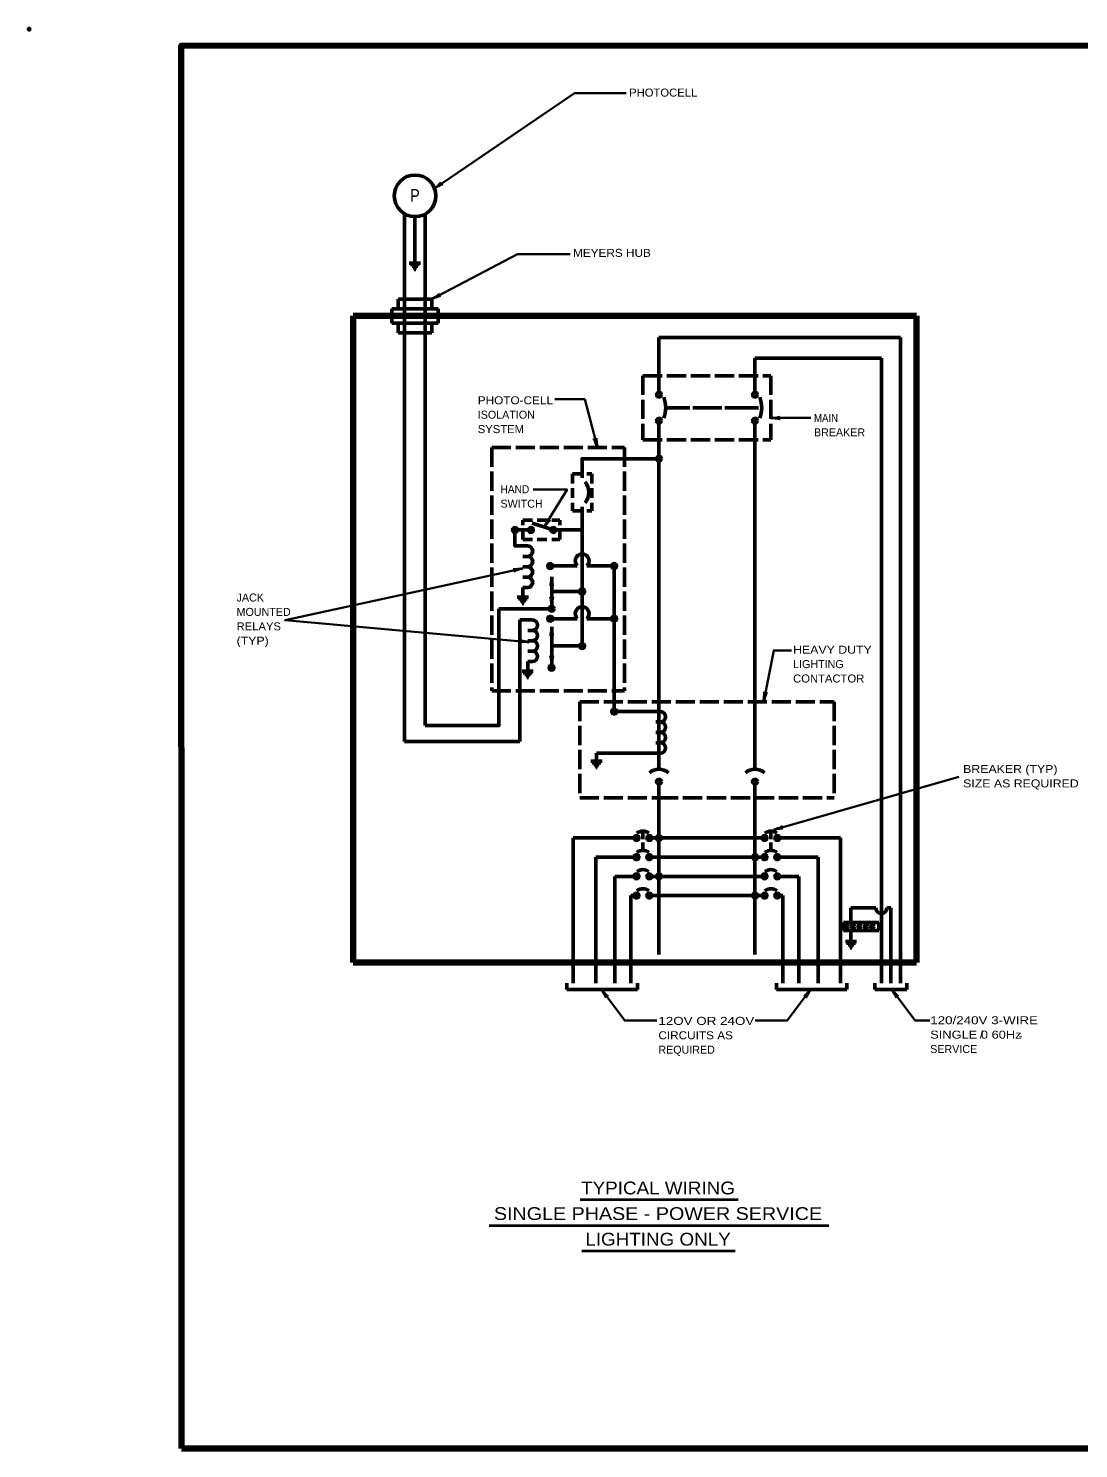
# Model space of a CAD drawing. Extents: x -35 to 821, y -18 to 526.
# Drawn here: x -35 to 359, y -7 to 526 of the extents above; entities that cross this region are included whole.
import ezdxf
from ezdxf.enums import TextEntityAlignment as Align

# ---------------------------------------------------------------- set-up
doc = ezdxf.new("R2010")
doc.units = 0
doc.header["$LTSCALE"] = 1.2
doc.header["$PDMODE"] = 32
doc.header["$PDSIZE"] = 0.6
doc.linetypes.add('LONG_DASHED', pattern=[7.5, 6, -1.5])
doc.linetypes.add('MEDIUM_DASHED', pattern=[4.5, 3, -1.5])
doc.layers.add('1', color=7, linetype='Continuous', lineweight=53)

msp = doc.modelspace()

# ---------------------------------------------------------------- hatches: boundary and pattern name
at = {"layer": '1'}
for points in [[(202.751, 364.268, 1), (200.951, 364.268, 1)], [(148.751, 337.568, 1), (146.951, 337.568, 1)], [(154.751, 337.568, 1), (152.951, 337.568, 1)], [(163.151, 337.568, 1), (161.351, 337.568, 1)], [(161.951, 324.068, 1), (160.151, 324.068, 1)], [(185.951, 324.068, 1), (184.151, 324.068, 1)], [(173.951, 314.468, 1), (172.151, 314.468, 1)], [(162.551, 308.018, 1), (160.751, 308.018, 1)], [(161.951, 304.268, 1), (160.151, 304.268, 1)], [(185.951, 304.268, 1), (184.151, 304.268, 1)], [(173.951, 294.068, 1), (172.151, 294.068, 1)], [(162.468, 285.943, 1), (160.668, 285.943, 1)], [(185.951, 269.468, 1), (184.151, 269.468, 1)], [(194.351, 222.068, 1), (192.551, 222.068, 1)], [(199.151, 222.068, 1), (197.351, 222.068, 1)], [(202.751, 222.068, 1), (200.951, 222.068, 1)], [(242.351, 222.068, 1), (240.551, 222.068, 1)], [(247.151, 222.068, 1), (245.351, 222.068, 1)], [(194.351, 214.868, 1), (192.551, 214.868, 1)], [(199.151, 214.868, 1), (197.351, 214.868, 1)], [(238.751, 214.868, 1), (236.951, 214.868, 1)], [(242.351, 214.868, 1), (240.551, 214.868, 1)], [(247.151, 214.868, 1), (245.351, 214.868, 1)], [(194.351, 207.668, 1), (192.551, 207.668, 1)], [(199.151, 207.668, 1), (197.351, 207.668, 1)], [(202.751, 207.668, 1), (200.951, 207.668, 1)], [(242.351, 207.668, 1), (240.551, 207.668, 1)], [(247.151, 207.668, 1), (245.351, 207.668, 1)], [(194.351, 200.468, 1), (192.551, 200.468, 1)], [(199.151, 200.468, 1), (197.351, 200.468, 1)], [(238.751, 200.468, 1), (236.951, 200.468, 1)], [(242.351, 200.468, 1), (240.551, 200.468, 1)], [(247.151, 200.468, 1), (245.351, 200.468, 1)], [(272.843, 188.918, 1), (271.642, 188.918, 1)], [(275.243, 188.918, 1), (274.043, 188.918, 1)], [(277.643, 188.918, 1), (276.442, 188.918, 1)], [(280.043, 188.918, 1), (278.842, 188.918, 1)], [(282.443, 188.918, 1), (281.243, 188.918, 1)]]:
    msp.add_hatch(color=256, dxfattribs=at).paths.add_polyline_path(points)

# ---------------------------------------------------------------- linework, layer by layer
for p, q in [((106.451, 456.122), (106.451, 258.218)), ((110.351, 437.638), (110.351, 455.038)), ((114.251, 456.044), (114.251, 264.218)), ((108.251, 437.638), (112.451, 437.638)), ((108.701, 437.038), (112.001, 437.038)), ((109.301, 436.438), (111.401, 436.438)), ((109.751, 435.838), (110.951, 435.838)), ((110.051, 435.238), (110.651, 435.238)), ((104.051, 424.118), (116.651, 424.118)), ((104.051, 424.118), (104.051, 420.518)), ((116.651, 424.118), (116.651, 420.518)), ((101.651, 420.518), (119.051, 420.518)), ((101.651, 420.518), (101.651, 415.118)), ((119.051, 420.518), (119.051, 415.118)), ((101.651, 415.118), (119.051, 415.118)), ((104.051, 411.518), (104.051, 415.118)), ((104.051, 411.518), (116.651, 411.518)), ((116.651, 411.518), (116.651, 415.118)), ((201.851, 409.718), (292.451, 409.718)), ((292.451, 409.718), (292.451, 167.618)), ((237.851, 401.918), (285.251, 401.918)), ((237.851, 389.168), (237.851, 401.918)), ((285.251, 401.918), (285.251, 167.618)), ((204.397, 383.393), (213.397, 383.393)), ((214.597, 383.393), (225.397, 383.393)), ((226.597, 383.393), (239.197, 383.393)), ((201.851, 377.618), (201.851, 247.868)), ((237.851, 377.618), (237.851, 247.868)), ((173.051, 314.468), (173.051, 346.268)), ((153.851, 337.568), (147.851, 337.568)), ((162.251, 337.568), (154.262, 340.164)), ((173.051, 337.568), (162.251, 337.568)), ((150.851, 327.668), (152.651, 327.668)), ((150.851, 323.768), (152.651, 323.768)), ((150.851, 319.868), (152.651, 319.868)), ((171.251, 324.068), (161.051, 324.068)), ((161.651, 308.918), (161.651, 320.018)), ((150.851, 315.968), (152.651, 315.968)), ((150.851, 315.968), (150.851, 312.368)), ((173.051, 314.468), (161.651, 314.468)), ((148.751, 312.368), (152.951, 312.368)), ((149.201, 311.768), (152.501, 311.768)), ((149.801, 311.168), (151.901, 311.168)), ((150.251, 310.568), (151.451, 310.568)), ((150.551, 309.968), (151.151, 309.968)), ((141.851, 308.018), (161.651, 308.018)), ((149.651, 258.218), (149.651, 303.818)), ((149.651, 303.818), (154.451, 303.818)), ((171.251, 304.268), (161.051, 304.268)), ((185.051, 304.268), (174.851, 304.268)), ((152.651, 299.918), (154.451, 299.918)), ((161.651, 286.868), (161.651, 301.268)), ((152.651, 296.018), (154.451, 296.018)), ((152.651, 292.118), (154.451, 292.118)), ((152.651, 288.218), (154.451, 288.218)), ((152.651, 288.218), (152.651, 284.618)), ((150.551, 284.618), (154.751, 284.618)), ((151.001, 284.018), (154.301, 284.018)), ((151.601, 283.418), (153.701, 283.418)), ((152.051, 282.818), (153.251, 282.818)), ((152.351, 282.218), (152.951, 282.218)), ((201.851, 269.468), (202.451, 269.468)), ((200.651, 265.568), (202.451, 265.568)), ((200.651, 261.668), (202.451, 261.668)), ((106.451, 258.218), (149.651, 258.218)), ((200.651, 257.768), (202.451, 257.768)), ((176.351, 250.868), (180.551, 250.868)), ((178.451, 253.868), (202.451, 253.868)), ((178.451, 253.868), (178.451, 250.868)), ((176.801, 250.268), (180.101, 250.268)), ((177.401, 249.668), (179.501, 249.668)), ((177.851, 249.068), (179.051, 249.068)), ((178.151, 248.468), (178.751, 248.468)), ((201.851, 242.318), (201.851, 178.418)), ((237.851, 242.318), (237.851, 178.418)), ((195.851, 224.012), (195.851, 221.612)), ((243.851, 224.012), (243.851, 221.612)), ((169.751, 222.068), (169.751, 167.618)), ((169.751, 222.068), (193.451, 222.068)), ((195.851, 220.412), (195.851, 218.012)), ((198.251, 222.068), (241.451, 222.068)), ((243.851, 220.412), (243.851, 218.012)), ((246.251, 222.068), (269.951, 222.068)), ((269.951, 222.068), (269.951, 167.618)), ((178.151, 214.868), (193.451, 214.868)), ((178.151, 214.868), (178.151, 167.618)), ((198.251, 214.868), (241.451, 214.868)), ((246.251, 214.868), (261.551, 214.868)), ((261.551, 214.868), (261.551, 167.618)), ((185.351, 207.668), (193.451, 207.668)), ((185.351, 207.668), (185.351, 167.618)), ((198.251, 207.668), (241.451, 207.668)), ((246.251, 207.668), (254.351, 207.668)), ((254.351, 207.668), (254.351, 167.618)), ((191.351, 200.468), (193.451, 200.468)), ((191.351, 200.468), (191.351, 167.618)), ((198.251, 200.468), (241.451, 200.468)), ((246.251, 200.468), (248.351, 200.468)), ((248.351, 200.468), (248.351, 167.618)), ((273.851, 195.818), (283.151, 195.818)), ((273.851, 195.818), (273.851, 190.418)), ((288.851, 195.818), (287.351, 195.818)), ((288.851, 195.818), (288.851, 167.618)), ((271.043, 190.418), (284.243, 190.418)), ((271.043, 190.418), (271.043, 187.418)), ((271.043, 187.418), (284.243, 187.418)), ((273.851, 187.418), (273.851, 183.218)), ((284.243, 190.418), (284.243, 187.418)), ((271.751, 183.218), (275.951, 183.218)), ((272.201, 182.618), (275.501, 182.618)), ((272.801, 182.018), (274.901, 182.018)), ((273.251, 181.418), (274.451, 181.418)), ((273.551, 180.818), (274.151, 180.818)), ((167.351, 165.218), (167.351, 167.618)), ((167.351, 165.218), (193.751, 165.218)), ((193.751, 165.218), (193.751, 167.618)), ((245.951, 165.218), (245.951, 167.618)), ((245.951, 165.218), (272.351, 165.218)), ((272.351, 165.218), (272.351, 167.618)), ((282.851, 165.218), (282.851, 167.618)), ((282.851, 165.218), (294.851, 165.218)), ((294.851, 165.218), (294.851, 167.618))]:
    msp.add_line(p, q, dxfattribs=at)
at = {"layer": '1', "lineweight": 140}
for p, q in [((87.251, 417.818), (87.251, 175.418)), ((87.251, 417.818), (298.451, 417.818)), ((298.451, 417.818), (298.451, 175.418)), ((87.251, 175.418), (298.451, 175.418))]:
    msp.add_line(p, q, dxfattribs=at)
at = {"layer": '1', "linetype": 'LONG_DASHED'}
for p, q in [((195.851, 395.393), (243.851, 395.393)), ((195.851, 395.393), (195.851, 371.393)), ((243.851, 395.393), (243.851, 371.393)), ((139.151, 368.468), (188.951, 368.468)), ((139.151, 368.468), (139.151, 277.268)), ((188.951, 368.468), (188.951, 277.268)), ((195.851, 371.393), (243.851, 371.393)), ((139.151, 277.268), (188.951, 277.268)), ((172.151, 273.068), (267.551, 273.068)), ((172.151, 273.068), (172.151, 237.068)), ((267.551, 273.068), (267.551, 237.068))]:
    msp.add_line(p, q, dxfattribs=at)
at = {"layer": '1', "lineweight": 35}
for p, q in [((243.851, 379.548), (258.801, 379.548)), ((244.885, 225.129), (314.285, 244.932))]:
    msp.add_line(p, q, dxfattribs=at)
at = {"layer": '1', "linetype": 'MEDIUM_DASHED'}
for p, q in [((169.451, 358.568), (176.651, 358.568)), ((169.451, 358.568), (169.451, 344.768)), ((176.651, 358.568), (176.651, 344.768)), ((150.851, 333.968), (150.851, 341.168)), ((150.851, 341.168), (164.651, 341.168)), ((164.651, 333.968), (164.651, 341.168)), ((169.451, 344.768), (176.651, 344.768)), ((150.851, 333.968), (164.651, 333.968))]:
    msp.add_line(p, q, dxfattribs=at)
at = {"layer": '1', "lineweight": 40}
for p, q in [((172.267, 86.576), (231.603, 86.576)), ((138.189, 76.743), (265.56, 76.743)), ((172.922, 67.237), (230.423, 67.237))]:
    msp.add_line(p, q, dxfattribs=at)
at = {"layer": '1', "lineweight": 158}
msp.add_line((814.433, -6.884), (22.833, -6.884), dxfattribs=at)
msp.add_lwpolyline([(814.433, 519.216), (22.733, 519.116), (22.833, -6.884)], dxfattribs=at)
at = {"layer": '1', "lineweight": 35}
for points in [[(117.696, 465.646), (170.154, 501.283), (189.594, 501.283)], [(116.651, 424.118), (148.77, 440.999), (168.599, 440.999)], [(178.757, 368.468), (174.042, 386.549), (162.767, 386.549)], [(158.855, 338.672), (167.433, 352.712), (154.739, 352.712)], [(150.714, 323.153), (61.678, 303.707), (153.047, 295.539)], [(241.121, 273.414), (244.913, 292.385), (251.523, 292.385)], [(180.361, 165.22), (189.063, 153.575), (201.058, 153.575)], [(258.679, 165.22), (249.977, 153.575), (237.982, 153.575)], [(289.2, 165.22), (297.902, 153.575), (303.472, 153.575)]]:
    msp.add_lwpolyline(points, dxfattribs=at)
at = {"layer": '1'}
for points in [[(201.851, 389.168), (201.851, 401.918), (201.851, 409.718)], [(173.051, 357.068), (173.051, 364.268), (201.851, 364.268)], [(147.851, 337.568), (147.851, 331.568), (152.651, 331.568)], [(185.051, 304.268), (185.051, 324.068), (174.851, 324.068)], [(173.051, 314.468), (173.051, 294.068), (161.651, 294.068)], [(114.251, 264.218), (141.851, 264.218), (141.851, 308.018)], [(185.051, 304.268), (185.051, 269.468), (201.851, 269.468)]]:
    msp.add_lwpolyline(points, dxfattribs=at)
at = {"layer": '1', "linetype": 'LONG_DASHED'}
msp.add_lwpolyline([(172.151, 237.068), (201.851, 237.068), (237.851, 237.068), (267.551, 237.068)], dxfattribs=at)
at = {"layer": '1'}
for centre, radius in [((110.419, 462.838), 7.8), ((201.851, 388.268), 0.9), ((237.851, 388.268), 0.9), ((201.851, 378.518), 0.9), ((237.851, 378.518), 0.9), ((201.851, 364.268), 0.9), ((147.851, 337.568), 0.9), ((153.851, 337.568), 0.9), ((162.251, 337.568), 0.9), ((161.051, 324.068), 0.9), ((185.051, 324.068), 0.9), ((173.051, 314.468), 0.9), ((161.651, 308.018), 0.9), ((161.051, 304.268), 0.9), ((185.051, 304.268), 0.9), ((173.051, 294.068), 0.9), ((161.568, 285.943), 0.9), ((185.051, 269.468), 0.9), ((201.851, 243.218), 0.9), ((237.851, 243.218), 0.9), ((193.451, 222.068), 0.9), ((198.251, 222.068), 0.9), ((201.851, 222.068), 0.9), ((241.451, 222.068), 0.9), ((246.251, 222.068), 0.9), ((193.451, 214.868), 0.9), ((198.251, 214.868), 0.9), ((237.851, 214.868), 0.9), ((241.451, 214.868), 0.9), ((246.251, 214.868), 0.9), ((193.451, 207.668), 0.9), ((198.251, 207.668), 0.9), ((201.851, 207.668), 0.9), ((241.451, 207.668), 0.9), ((246.251, 207.668), 0.9), ((193.451, 200.468), 0.9), ((198.251, 200.468), 0.9), ((237.851, 200.468), 0.9), ((241.451, 200.468), 0.9), ((246.251, 200.468), 0.9), ((272.243, 188.918), 0.6), ((274.643, 188.918), 0.6), ((277.043, 188.918), 0.6), ((279.442, 188.918), 0.6), ((281.843, 188.918), 0.6)]:
    msp.add_circle(centre, radius, dxfattribs=at)
for centre, radius, start, end in [((193.433, 383.393), 10.964, 338.74274, 21.25726), ((229.433, 383.393), 10.964, 338.74274, 21.25726), ((169.048, 351.668), 6.503, 323.14889, 36.85111), ((152.568, 329.618), 1.952, 272.45324, 87.54675), ((152.568, 325.718), 1.952, 272.45324, 87.54675), ((173.051, 325.951), 2.604, 313.71808, 226.28192), ((152.568, 321.818), 1.952, 272.45324, 87.54675), ((152.568, 317.918), 1.952, 272.45324, 87.54675), ((154.368, 301.868), 1.952, 272.45324, 87.54675), ((173.051, 306.151), 2.604, 313.71808, 226.28192), ((154.368, 297.968), 1.952, 272.45324, 87.54675), ((154.368, 294.068), 1.952, 272.45324, 87.54675), ((154.368, 290.168), 1.952, 272.45324, 87.54675), ((202.368, 267.518), 1.952, 272.45324, 87.54675), ((202.368, 263.618), 1.952, 272.45324, 87.54675), ((202.368, 259.718), 1.952, 272.45324, 87.54675), ((202.368, 255.818), 1.952, 272.45324, 87.54675), ((201.851, 242.393), 5.475, 48.88791, 131.11209), ((237.851, 242.393), 5.475, 48.88791, 131.11209), ((195.851, 220.837), 3.775, 53.41416, 126.58584), ((243.851, 220.837), 3.775, 53.41416, 126.58584), ((195.851, 213.637), 3.775, 53.41416, 126.58584), ((243.851, 213.637), 3.775, 53.41416, 126.58584), ((195.851, 206.437), 3.775, 53.41416, 126.58584), ((243.851, 206.437), 3.775, 53.41416, 126.58584), ((195.851, 199.237), 3.775, 53.41416, 126.58584), ((243.851, 199.237), 3.775, 53.41416, 126.58584), ((285.251, 195.841), 2.1, 180.62582, 359.37418)]:
    msp.add_arc(centre, radius, start, end, dxfattribs=at)
at = {"layer": '1', "lineweight": 40}
for centre, major_axis, ratio, start_param, end_param in [((118.593, 466.656), (-1.667, -1.359), 0.122415, 0.8963533, 3.1415927), ((118.951, 466.192), (1.862, 1.01), 0.07063, 6.2823074, 8.5597026), ((117.656, 425.021), (-1.81, -1.163), 0.122415, 0.8963533, 3.1415927), ((117.656, 425.021), (-1.81, -1.163), 0.122415, 0.8963533, 3.1415927), ((117.96, 424.519), (-1.964, -0.794), 0.07063, 3.1407148, 5.41811), ((117.96, 424.519), (-1.964, -0.794), 0.07063, 3.1407148, 5.41811), ((245.196, 379.294), (-2.108, 0.211), 0.07063, 3.1407148, 5.41811), ((245.196, 379.294), (-2.108, 0.211), 0.07063, 3.1407148, 5.41811), ((245.161, 379.879), (-2.143, -0.187), 0.122415, 0.8963533, 3.1415927), ((245.161, 379.879), (-2.143, -0.187), 0.122415, 0.8963533, 3.1415927), ((178.106, 369.652), (0.722, -2.026), 0.122415, 0.8963533, 3.1415927), ((178.106, 369.652), (0.722, -2.026), 0.122415, 0.8963533, 3.1415927), ((178.664, 369.834), (0.328, -2.093), 0.07063, 3.1407148, 5.41811), ((178.664, 369.834), (0.328, -2.093), 0.07063, 3.1407148, 5.41811), ((159.255, 339.962), (-0.957, -1.926), 0.122415, 0.8963533, 3.1415927), ((159.255, 339.962), (-0.957, -1.926), 0.122415, 0.8963533, 3.1415927), ((159.773, 339.687), (1.279, 1.689), 0.07063, 6.2823074, 8.5597026), ((159.773, 339.687), (1.279, 1.689), 0.07063, 6.2823074, 8.5597026), ((149.346, 323.114), (-2.104, -0.244), 0.07063, 6.2823074, 8.5597026), ((149.346, 323.114), (-2.104, -0.244), 0.07063, 6.2823074, 8.5597026), ((149.505, 322.55), (2.054, 0.64), 0.122415, 0.8963533, 3.1415927), ((149.505, 322.55), (2.054, 0.64), 0.122415, 0.8963533, 3.1415927), ((161.397, 318.674), (0.211, 2.108), 0.07063, 3.1407148, 5.41811), ((161.983, 318.709), (-0.187, 2.143), 0.122415, 0.8963533, 3.1415927), ((161.32, 310.228), (0.187, -2.143), 0.122415, 0.8963533, 3.1415927), ((161.905, 310.263), (-0.211, -2.108), 0.07063, 3.1407148, 5.41811), ((161.397, 299.924), (0.211, 2.108), 0.07063, 3.1407148, 5.41811), ((161.983, 299.959), (-0.187, 2.143), 0.122415, 0.8963533, 3.1415927), ((151.713, 295.326), (2.151, -0.004), 0.122415, 0.8963533, 3.1415927), ((151.713, 295.326), (2.151, -0.004), 0.122415, 0.8963533, 3.1415927), ((151.73, 295.912), (-2.081, 0.398), 0.07063, 6.2823074, 8.5597026), ((151.73, 295.912), (-2.081, 0.398), 0.07063, 6.2823074, 8.5597026), ((161.32, 288.178), (0.187, -2.143), 0.122415, 0.8963533, 3.1415927), ((161.905, 288.213), (-0.211, -2.108), 0.07063, 3.1407148, 5.41811), ((241.052, 274.763), (-0.236, -2.138), 0.122415, 0.8963533, 3.1415927), ((241.633, 274.683), (0.62, 2.026), 0.07063, 6.2823074, 8.5597026), ((246.053, 225.807), (-2.009, -0.768), 0.122415, 0.8963533, 3.1415927), ((246.247, 225.254), (2.085, 0.376), 0.07063, 6.2823074, 8.5597026), ((180.963, 163.991), (1.093, -1.815), 0.07063, 6.2823074, 8.5597026), ((181.411, 164.37), (-1.433, 1.604), 0.122415, 0.8963533, 3.1415927), ((257.629, 164.37), (1.433, 1.604), 0.122415, 3.1415927, 5.386832), ((258.077, 163.991), (-1.093, -1.815), 0.07063, 4.006668, 6.2840632), ((289.801, 163.991), (1.093, -1.815), 0.07063, 6.2823074, 8.5597026), ((290.249, 164.37), (-1.433, 1.604), 0.122415, 0.8963533, 3.1415927)]:
    msp.add_ellipse(centre, major_axis=major_axis, ratio=ratio, start_param=start_param, end_param=end_param, dxfattribs=at)
at = {"layer": '1'}
msp.add_point((-34.267, 525.316), dxfattribs=at)

# ---------------------------------------------------------------- texts
for s, height, width, p in [('PHOTOCELL', 3, 1.05, (190.687, 500.05)), ('P', 4.8, 0.85, (108.529, 460.591)), ('MEYERS HUB', 3, 1.1, (169.638, 439.959)), ('PHOTO-CELL', 3, 1.1, (133.927, 384.675)), ('MAIN', 3, 0.9, (259.982, 378.051)), ('SYSTEM', 3, 1.05, (133.927, 373.875)), ('HAND', 3, 0.95, (142.441, 351.317)), ('RELAYS', 3, 1.05, (43.495, 299.931)), ('(TYP)', 3, 1.15, (43.495, 294.531)), ('HEAVY DUTY', 3, 1.15, (252.16, 291.16)), ('CONTACTOR', 3, 1.05, (252.16, 280.36)), ('BREAKER (TYP)', 3, 1.15, (315.909, 246.429)), ('SIZE AS REQUIRED', 3, 1.15, (315.909, 241.029)), ('12OV OR 24OV', 3, 1.25, (201.646, 151.986)), ('120/240V 3-WIRE', 3, 1.25, (303.562, 152.225)), ('CIRCUITS AS', 3, 1.1, (201.646, 146.586)), ('SINGLE 0 60Hz', 3, 1.2, (303.562, 146.825))]:
    msp.add_text(s, height=height, dxfattribs=dict(at, width=width)).set_placement(p)
for s, p in [('ISOLATION', (133.927, 379.275)), ('BREAKER', (259.982, 372.651)), ('SWITCH', (142.441, 345.917)), ('JACK', (43.495, 310.731)), ('MOUNTED', (43.495, 305.331)), ('LIGHTING', (252.16, 285.76)), ('/', (322.166, 146.843)), ('REQUIRED', (201.646, 141.186)), ('SERVICE', (303.562, 141.425)), ('-', (336.773, 146.356))]:
    msp.add_text(s, height=3, dxfattribs=at).set_placement(p)
for s, width, p in [('TYPICAL WIRING', 1.1, (201.505, 88.434)), ('SINGLE PHASE - POWER SERVICE', 1.15, (201.505, 78.834)), ('LIGHTING ONLY', 1.1, (201.505, 69.234))]:
    msp.add_text(s, height=4.8, dxfattribs=dict(at, width=width)).set_placement(p, align=Align.CENTER)

doc.saveas('drawing.dxf')
